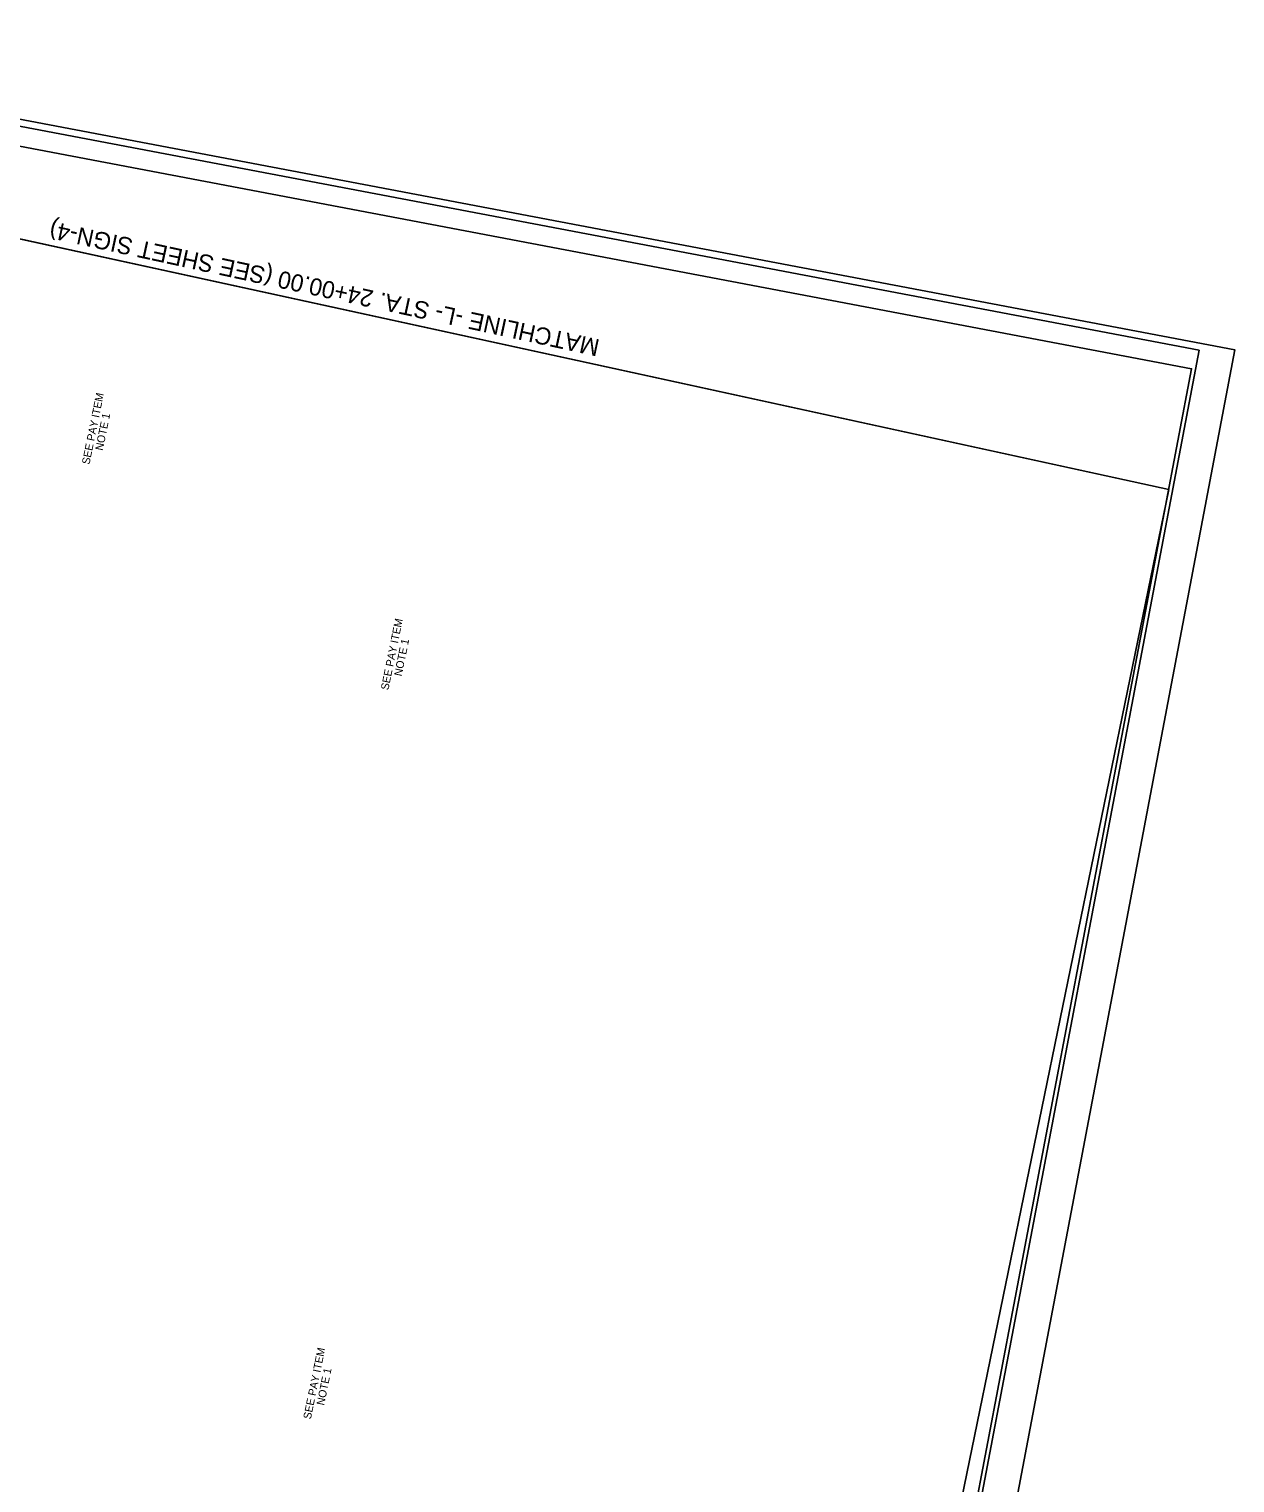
# Model space of a CAD drawing. Extents: x 1615681 to 1617075, y 899309 to 901168.
# Drawn here: x 1616304 to 1617075, y 900239 to 901168 of the extents above; entities that cross this region are included whole.
import ezdxf

# ---------------------------------------------------------------- set-up
doc = ezdxf.new("R2010")
doc.units = 0
for name, color, linetype in [('CTL Primary Horizontal and Vertical CELL', 7, 'Continuous'), ('CTL Primary Horizontal and Vertical Cogo Number', 7, 'Continuous'), ('CTL Secondary Horizontal and Vertical CELL', 7, 'Continuous'), ('Default', 7, 'Continuous'), ('Exist DTM Crownline Cogo Number', 7, 'Continuous'), ('Exist Roads Curbs Cogo Number', 7, 'Continuous'), ('Exist Roads Curbs Cogo Point CELL', 7, 'Continuous')]:
    doc.layers.add(name, color=color, linetype=linetype)

msp = doc.modelspace()

# ---------------------------------------------------------------- linework, layer by layer
at = {"layer": 'CTL Primary Horizontal and Vertical CELL'}
msp.add_lwpolyline([(1616015.87, 901159.82), (1615705.01, 899522.57), (1616741.59, 899325.76), (1617052.45, 900963.01)], close=True, dxfattribs=at)
at = {"layer": 'CTL Primary Horizontal and Vertical Cogo Number'}
msp.add_lwpolyline([(1615994.65, 901168.43), (1615680.53, 899513.99), (1616761.22, 899308.8), (1617075.34, 900963.24)], close=True, dxfattribs=at)
at = {"layer": 'CTL Secondary Horizontal and Vertical CELL'}
msp.add_lwpolyline([(1616016.04, 901147.07), (1615736.24, 899673.39), (1616767.81, 899477.53), (1617047.61, 900951.21)], close=True, dxfattribs=at)
at = {"layer": 'Exist DTM Crownline Cogo Number'}
msp.add_lwpolyline([(1616176.29, 901060.7), (1617032.97, 900874.07), (1616753.23, 899510.43), (1615915.8, 899646.19), (1615751.76, 899738.03), (1615999.36, 900929.08), (1616157.93, 900902)], close=True, dxfattribs=at)
at = {"layer": 'Exist Roads Curbs Cogo Point CELL'}
msp.add_line((1616196.89, 901056.22), (1617032.97, 900874.07), dxfattribs=at)

# ---------------------------------------------------------------- texts
at = {"layer": 'Default'}
for s, p in [('SEE PAY ITEM', (1616342.69, 900889.71)), ('NOTE 1', (1616351.19, 900898.57)), ('SEE PAY ITEM', (1616533.88, 900745.39)), ('NOTE 1', (1616542.38, 900754.25)), ('SEE PAY ITEM', (1616484.27, 900279.06)), ('NOTE 1', (1616492.77, 900287.92))]:
    msp.add_text(s, height=5, rotation=78.45796, dxfattribs=at).set_placement(p)
at = {"layer": 'Exist Roads Curbs Cogo Number'}
msp.add_text('MATCHLINE -L- STA. 24+00.00 (SEE SHEET SIGN-4)', height=11, rotation=167.79564, dxfattribs=at).set_placement((1616669.63, 900969.75))

doc.saveas('drawing.dxf')
